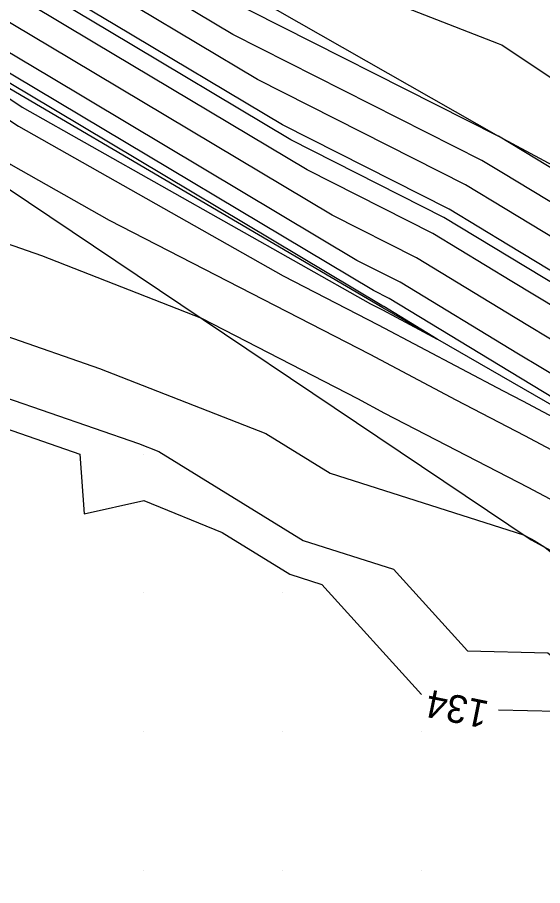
# Model space of a CAD drawing. Extents: x 2354170 to 2357230, y 866100 to 868290.
# Drawn here: x 2355080.9 to 2355118.7, y 867388.9 to 867451.5 of the extents above; entities that cross this region are included whole.
import ezdxf

# ---------------------------------------------------------------- set-up
doc = ezdxf.new("R2010")
doc.units = 0
for name, color, linetype in [('Default', 7, 'Continuous'), ('DTM Contours Major', 7, 'Continuous'), ('DTM Contours Minor', 7, 'Continuous'), ('Exist DTM QL2 LIDAR Elevation Point', 7, 'Continuous'), ('PH Exist DTM Breakline', 7, 'Continuous')]:
    doc.layers.add(name, color=color, linetype=linetype)

msp = doc.modelspace()

# ---------------------------------------------------------------- linework, layer by layer
at = {"layer": 'Default'}
for points in [[(2355206.096, 867387.294), (2355185.909, 867398.139), (2355178.94, 867402.004), (2355174.728, 867404.556), (2355173.329, 867405.33), (2355154.767, 867416.578), (2355149.648, 867419.858), (2355142.273, 867424.313), (2355136.401, 867427.874), (2355115.792, 867440.318), (2355114.362, 867441.184), (2355096.389, 867450.283), (2355091.031, 867453.482), (2355087.865, 867455.371), (2355066.977, 867466.192), (2355056.212, 867473.168), (2355050.043, 867476.946), (2355048.239, 867478.051), (2355028.572, 867490.861), (2355022.85, 867493.658), (2355017.964, 867496.138), (2355001.26, 867504.616)], [(2355203.95, 867386.004), (2355186.849, 867395.191), (2355176.771, 867400.781), (2355173.32, 867402.872), (2355171.283, 867403.999), (2355156.186, 867413.147), (2355148.501, 867418.072), (2355142.442, 867421.732), (2355133.164, 867427.358), (2355116.033, 867437.702), (2355113.183, 867439.43), (2355098.181, 867447.024), (2355089.462, 867452.229), (2355084.311, 867455.304), (2355066.768, 867464.392), (2355057.726, 867470.251), (2355048.431, 867475.944), (2355045.713, 867477.609), (2355029.297, 867488.301), (2355019.493, 867493.093), (2355015.668, 867495.035), (2355002.591, 867501.672)], [(2355199.66, 867383.423), (2355188.73, 867389.295), (2355172.434, 867398.335), (2355170.503, 867399.504), (2355167.192, 867401.336), (2355159.025, 867406.285), (2355146.207, 867414.5), (2355142.78, 867416.57), (2355126.689, 867426.327), (2355116.516, 867432.47), (2355110.824, 867435.921), (2355101.765, 867440.506), (2355086.325, 867449.723), (2355077.203, 867455.169), (2355066.348, 867460.792), (2355060.754, 867464.417), (2355045.207, 867473.939), (2355040.661, 867476.724), (2355030.748, 867483.18), (2355012.78, 867491.964), (2355011.076, 867492.829)], [(2355189.67, 867386.347), (2355170.265, 867397.112), (2355169.095, 867397.82), (2355165.146, 867400.005), (2355160.445, 867402.854), (2355145.059, 867412.714), (2355142.949, 867413.989), (2355123.452, 867425.811), (2355116.757, 867429.854), (2355109.644, 867434.166), (2355103.557, 867437.248), (2355084.757, 867448.471), (2355073.649, 867455.101), (2355066.139, 867458.992), (2355062.268, 867461.5), (2355043.595, 867472.937), (2355038.135, 867476.281), (2355031.474, 867480.62), (2355009.423, 867491.399)], [(2355011.355, 867485.087), (2355022.248, 867475.786), (2355040.677, 867462.719), (2355042.494, 867461.078), (2355042.9, 867460.65), (2355043.286, 867460.521), (2355044.376, 867459.604), (2355045.15, 867458.816), (2355066.333, 867443.989), (2355068.736, 867442.505), (2355070.396, 867442.401), (2355077.964, 867437.351), (2355080.037, 867435.225), (2355082.594, 867434.338), (2355094.134, 867429.811), (2355105.377, 867424.03), (2355107.346, 867422.985), (2355117.673, 867417.65), (2355127.775, 867412.283), (2355144.078, 867401.508), (2355145.731, 867400.416), (2355149.423, 867398.409), (2355151.647, 867395.803), (2355161.45, 867386.039)], [(2355053.159, 867458.209), (2355069.077, 867447.905), (2355073.8, 867445.227), (2355080.38, 867440.9), (2355087.474, 867436.895), (2355106.28, 867427.224), (2355112.476, 867423.938), (2355117.438, 867421.374), (2355137.405, 867410.766), (2355143.543, 867406.709), (2355144.165, 867406.298), (2355158.966, 867398.254), (2355165.456, 867390.645), (2355166.394, 867389.601), (2355167.828, 867388.006)], [(2355193.792, 867398.789), (2355184.028, 867404.035), (2355183.278, 867404.451), (2355177.545, 867407.923), (2355177.42, 867407.992), (2355152.665, 867422.993), (2355151.999, 867423.427), (2355151.93, 867423.467), (2355142.851, 867430.204), (2355142.017, 867430.768), (2355124.361, 867443.775), (2355115.793, 867449.502), (2355115.558, 867449.59), (2355097.876, 867456.495)], [(2355190.611, 867383.399), (2355168.096, 867395.889), (2355167.686, 867396.137), (2355163.1, 867398.674), (2355161.864, 867399.423), (2355143.912, 867410.928), (2355143.118, 867411.408), (2355120.215, 867425.295), (2355116.998, 867427.238), (2355108.465, 867432.412), (2355105.349, 867433.989), (2355083.188, 867447.218), (2355070.096, 867455.034)], [(2355042.104, 867454.659), (2355047.668, 867448.996), (2355057.788, 867441.914), (2355065.136, 867437.374), (2355070.213, 867437.057), (2355074.515, 867434.186), (2355080.009, 867428.554), (2355086.785, 867426.204), (2355098.776, 867421.5), (2355103.407, 867418.649), (2355117.357, 867414.21), (2355117.908, 867413.926), (2355118.144, 867413.8), (2355118.895, 867413.304), (2355135.604, 867399.703), (2355139.304, 867396.22), (2355142.633, 867395.888), (2355143.737, 867395.078), (2355147.629, 867391.635), (2355156.078, 867383.219)], [(2355167.675, 867403.615), (2355157.606, 867409.716), (2355147.354, 867416.286), (2355142.611, 867419.151), (2355129.927, 867426.843), (2355116.274, 867435.086), (2355112.003, 867437.675), (2355099.973, 867443.765), (2355087.894, 867450.976), (2355081.728, 867454.657)], [(2355031.523, 867453.204), (2355032.542, 867452.13), (2355038.878, 867450.016), (2355039.166, 867449.21), (2355039.972, 867448.099), (2355047.478, 867440.016), (2355048.471, 867438.515), (2355049.972, 867438.119), (2355051.616, 867438.372), (2355061.535, 867432.243), (2355070.03, 867431.712), (2355071.067, 867431.02), (2355079.98, 867421.883), (2355085.364, 867420.015), (2355085.674, 867415.717), (2355089.972, 867416.682), (2355095.617, 867414.37), (2355100.508, 867411.361), (2355102.825, 867410.623), (2355110.009, 867402.699)], [(2355066.341, 867453.559), (2355080.246, 867445.674), (2355081.209, 867445.041), (2355106.317, 867430.864), (2355107.184, 867430.418), (2355111.142, 867428.319), (2355107.285, 867430.657), (2355107.141, 867430.73), (2355081.62, 867445.965), (2355069.446, 867453.232)], [(2355181.84, 867402.822), (2355181.109, 867403.228), (2355176.136, 867406.24), (2355175.375, 867406.661), (2355153.348, 867420.009), (2355150.796, 867421.644), (2355142.104, 867426.894), (2355139.638, 867428.39), (2355115.551, 867442.934), (2355115.542, 867442.939), (2355095.461, 867453.104)], [(2355115.557, 867401.578), (2355119.754, 867401.484), (2355121.599, 867399.983), (2355131.271, 867390.878), (2355139.933, 867390.015), (2355139.951, 867389.993), (2355139.973, 867389.991), (2355140.02, 867389.968), (2355149.691, 867381.411), (2355150.707, 867380.4), (2355160.315, 867380.479), (2355169.971, 867370.026), (2355169.984, 867370.016), (2355181.071, 867361.158), (2355181.642, 867360.685), (2355190.263, 867350.695), (2355195.258, 867350.424)]]:
    msp.add_lwpolyline(points, dxfattribs=at)
at = {"layer": 'DTM Contours Major'}
msp.add_lwpolyline([(2355181.84, 867402.822), (2355181.109, 867403.228), (2355176.136, 867406.24), (2355175.375, 867406.661), (2355153.348, 867420.009), (2355150.796, 867421.644), (2355142.104, 867426.894), (2355139.638, 867428.39), (2355115.551, 867442.934), (2355115.542, 867442.939), (2355095.461, 867453.104)], dxfattribs=at)
at = {"layer": 'DTM Contours Minor'}
for points in [[(2355197.941, 867385.975), (2355188.103, 867391.26), (2355173.88, 867399.15), (2355171.442, 867400.627), (2355168.555, 867402.224), (2355158.079, 867408.572), (2355146.972, 867415.691), (2355142.667, 867418.291), (2355128.848, 867426.671), (2355116.355, 867434.214), (2355111.61, 867437.09), (2355100.57, 867442.679), (2355087.371, 867450.559), (2355079.573, 867455.214), (2355066.488, 867461.992), (2355059.745, 867466.362), (2355046.281, 867474.608), (2355042.345, 867477.019), (2355030.265, 867484.887), (2355025.573, 867487.181)], [(2355067.253, 867451.674), (2355078.097, 867445.525), (2355080.933, 867443.66), (2355100.036, 867432.874), (2355106.883, 867429.353), (2355115.896, 867424.573), (2355117.282, 867423.857), (2355138.126, 867412.782), (2355118.057, 867424.952), (2355117.159, 867425.494), (2355107.678, 867431.242), (2355106.544, 867431.816), (2355082.143, 867446.383), (2355067.726, 867454.988), (2355065.789, 867455.992), (2355064.791, 867456.639), (2355040.908, 867471.267), (2355036.07, 867474.229)], [(2355011.222, 867471.873), (2355014.706, 867470.172), (2355018.579, 867468.694), (2355027.779, 867460.384), (2355034.268, 867453.55), (2355040.437, 867451.491), (2355040.59, 867451.363), (2355049.347, 867442.45), (2355052.09, 867440.53), (2355062.735, 867433.954), (2355070.091, 867433.494), (2355072.216, 867432.075), (2355079.99, 867424.106), (2355089.578, 867420.781), (2355091.061, 867420.199), (2355101.474, 867413.79), (2355107.978, 867411.72), (2355113.315, 867405.833), (2355119.125, 867405.703), (2355126.267, 867399.889), (2355133.949, 867392.659), (2355140.858, 867391.97), (2355141.226, 867391.701), (2355149.004, 867384.819)]]:
    msp.add_lwpolyline(points, dxfattribs=at)
at = {"layer": 'Exist DTM QL2 LIDAR Elevation Point'}
for p, q in [((2355089.972, 867420.015), (2355089.972, 867420.015)), ((2355089.972, 867410.015), (2355089.972, 867410.015)), ((2355099.972, 867410.015), (2355099.972, 867410.015)), ((2355089.972, 867400.015), (2355089.972, 867400.015)), ((2355099.972, 867400.015), (2355099.972, 867400.015)), ((2355109.973, 867400.015), (2355109.973, 867400.015)), ((2355089.972, 867390.015), (2355089.972, 867390.015)), ((2355099.972, 867390.015), (2355099.972, 867390.015)), ((2355109.973, 867390.015), (2355109.973, 867390.015))]:
    msp.add_line(p, q, dxfattribs=at)
at = {"layer": 'PH Exist DTM Breakline'}
for points in [[(2354996.831, 867514.414), (2355027.555, 867494.45), (2355067.458, 867470.316), (2355115.549, 867442.95), (2355151.936, 867423.42), (2355183.801, 867404.746), (2355224.702, 867380.361), (2355253.602, 867357.834), (2355263.9, 867342.784), (2355274.845, 867316.014), (2355275.719, 867309.171), (2355280.403, 867284.339)], [(2355212.697, 867365.916), (2355192.061, 867378.852), (2355162.37, 867398.199), (2355143.22, 867409.85), (2355107.228, 867430.572), (2355065.668, 867454.949), (2355032.96, 867475.375), (2354991.364, 867500.884)], [(2354985.838, 867493.756), (2355017.41, 867475.972), (2355044.743, 867460.403), (2355080.054, 867439.27), (2355117.914, 867413.837), (2355146.252, 867398.461), (2355166.298, 867388.584), (2355197.167, 867366.916)]]:
    msp.add_lwpolyline(points, dxfattribs=at)

# ---------------------------------------------------------------- texts
at = {"layer": 'Default'}
msp.add_text('134', height=2, rotation=168.58329, dxfattribs=at).set_placement((2355114.955, 867402.182))

doc.saveas('drawing.dxf')
